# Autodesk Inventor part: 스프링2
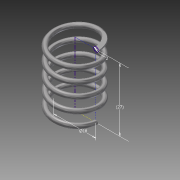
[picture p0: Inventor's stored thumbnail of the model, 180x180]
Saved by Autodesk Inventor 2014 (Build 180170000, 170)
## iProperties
Created: 2016-10
Part Number: 스프링2
Material: Steel, Carbon
Document SubType Name: Modeling
Designer: user
Mass: 6.88058 g
Surface Area: 17.7464 cm^2
Volume: 0.87428 cm^3
Density: 7.87 g/cm^3
Appearance: Semi-Polished
Author: user
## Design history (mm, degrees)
sketch "Sketch1"
  geometry: L1 (0, 0)-(-9, 0); L2 (-9, 0)-(-9, -26); L3 (-9, -26)-(0, -26); L4 (0, -26)-(0, 0); C1 r 1 at (-9, 0)
  constraints: 8 end point, 2 parallel, 1 centre point, 1 coincident, 1 horizontal, 1 perpendicular
  dimensions: "d0" = 26 distance of L1.end L2.end (derived); "d1" = 2 diameter of C1; "d2" = 18 diameter of L2 L4
coil "Coil1" pitch "d3" = 10; turns "d5" = 5; dims "d4" = 26 (= d0), "d6" = 0, angle "d7" = 90 deg, angle "d8" = 90 deg, "d9" = 0, "d10" = 0
sketch "Sketch2"
  geometry: L1 (10, 0)-(8, 0) reference; L2 (10, 0)-(8, 0) reference; 1 further point
  constraints: 2 horizontal alignment
extrude "Extrusion1" cut sketch "Sketch2" stored distance "d11" = 10; taper "d12" = 0 deg
workplane "Work Plane1"
sketch "Sketch3"
  geometry: L1 (-1, 0)-(1, 0) reference; 1 further point
  constraints: 1 horizontal alignment
extrude "Extrusion2" cut sketch "Sketch3" stored distance "d14" = 10; taper "d15" = 0 deg
body "Solid1"
node "Project Cut Edges1"
node "Project Cut Edges2"
node "Project Cut Edges3"
other parameters: "d13" = 90 deg
